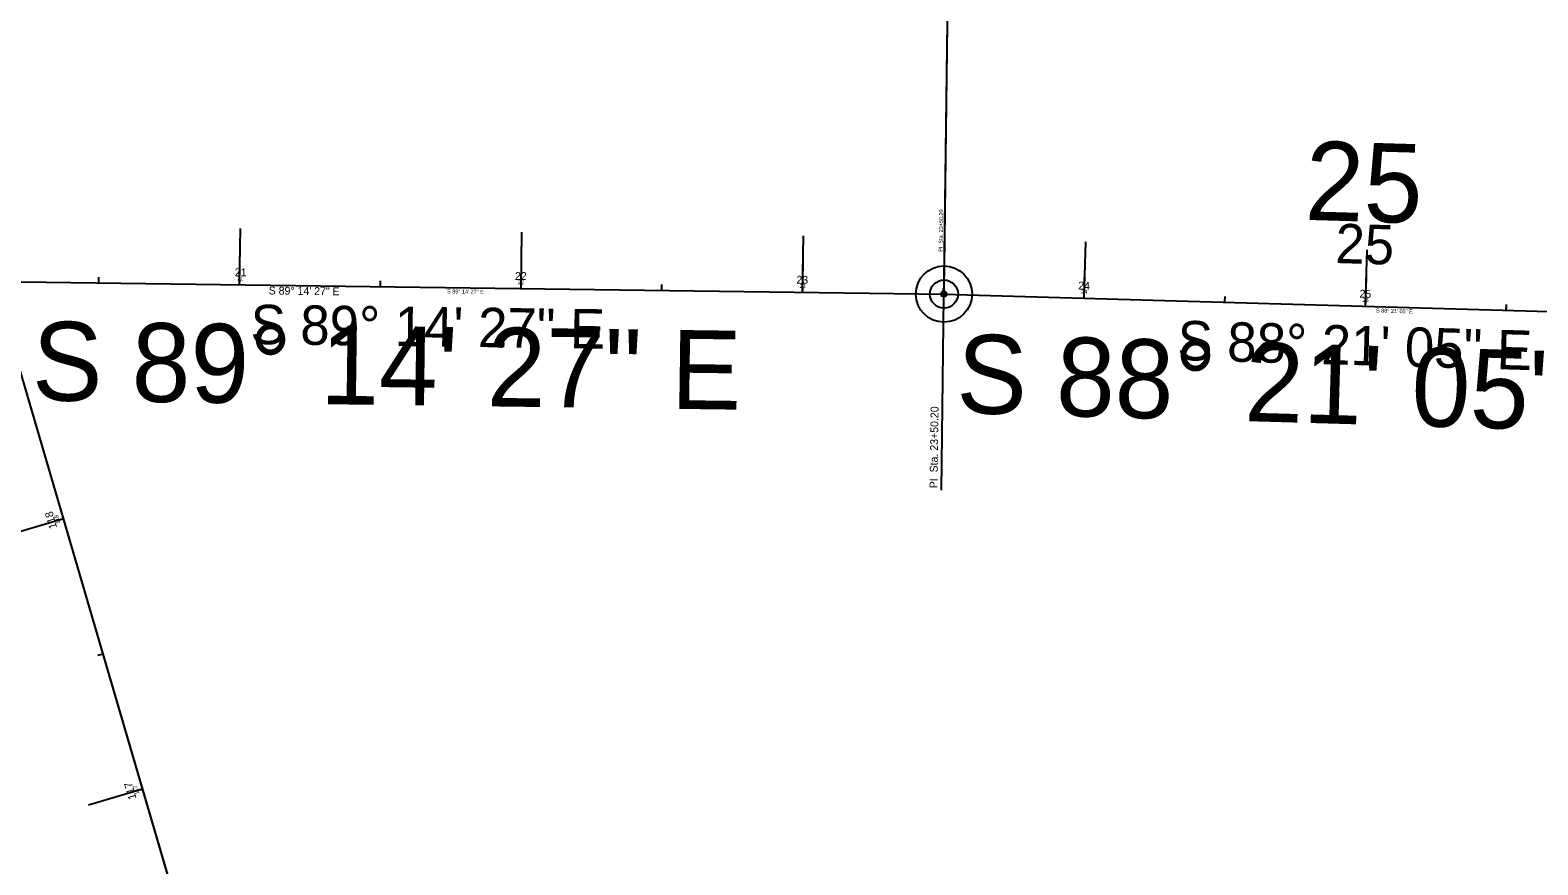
# Model space of a CAD drawing. Extents: x 1794716 to 1797874, y 325521 to 329174.
# Drawn here: x 1796283 to 1796818, y 327317 to 327614 of the extents above; entities that cross this region are included whole.
import ezdxf

# ---------------------------------------------------------------- set-up
doc = ezdxf.new("R2010")
doc.units = 0
for name, color, linetype in [('GE_P_CL_10', 7, 'Continuous'), ('GE_P_CL_100', 7, 'Continuous'), ('GE_P_CL_20', 7, 'Continuous'), ('GE_P_CL_200', 7, 'Continuous'), ('GE_P_CL_25', 7, 'Continuous'), ('GE_X_CL_30', 7, 'Continuous'), ('RW_X_CL_20', 7, 'Continuous')]:
    doc.layers.add(name, color=color, linetype=linetype)

msp = doc.modelspace()

# ---------------------------------------------------------------- linework, layer by layer
at = {"layer": 'GE_P_CL_10'}
for p, q in [((1796607.38, 327520.54), (1796607.83, 327554.83)), ((1796800.73, 325712.87), (1796269.93, 327524.51)), ((1796269.93, 327524.51), (1796607.37, 327520.04)), ((1796307.2, 327524.02), (1796307.21, 327525.02)), ((1796357.19, 327523.35), (1796357.2, 327524.35)), ((1796407.19, 327522.69), (1796407.2, 327523.69)), ((1796457.18, 327522.03), (1796457.2, 327523.03)), ((1796507.18, 327521.37), (1796507.19, 327522.37)), ((1796557.17, 327520.7), (1796557.19, 327521.7)), ((1796607.17, 327520.04), (1796607.18, 327521.04)), ((1796607.37, 327520.04), (1796930, 327510.75)), ((1796657.15, 327518.61), (1796657.18, 327519.61)), ((1796707.13, 327517.17), (1796707.16, 327518.17)), ((1796757.11, 327515.73), (1796757.14, 327516.73)), ((1796807.09, 327514.29), (1796807.12, 327515.29)), ((1796294.62, 327440.25), (1796293.66, 327439.97)), ((1796308.67, 327392.27), (1796307.72, 327391.99)), ((1796322.73, 327344.29), (1796321.77, 327344.01))]:
    msp.add_line(p, q, dxfattribs=at)
msp.add_circle((1796607.37, 327520.04), 0.5, dxfattribs=at)
at = {"layer": 'GE_P_CL_100'}
for p, q in [((1796607.43, 327525.04), (1796611.32, 327817.91)), ((1796357.19, 327523.35), (1796357.32, 327533.35)), ((1796457.18, 327522.03), (1796457.31, 327532.03)), ((1796557.17, 327520.7), (1796557.31, 327530.7)), ((1796657.15, 327518.61), (1796657.44, 327528.6)), ((1796800.73, 325712.87), (1796269.93, 327524.51)), ((1796269.93, 327524.51), (1796607.37, 327520.04)), ((1796757.11, 327515.73), (1796757.39, 327525.73)), ((1796607.37, 327520.04), (1796930, 327510.75)), ((1796294.62, 327440.25), (1796285.02, 327437.44)), ((1796322.73, 327344.29), (1796313.14, 327341.47))]:
    msp.add_line(p, q, dxfattribs=at)
msp.add_circle((1796607.37, 327520.04), 5, dxfattribs=at)
at = {"layer": 'GE_P_CL_20'}
for p, q in [((1796800.73, 325712.87), (1796269.93, 327524.51)), ((1796269.93, 327524.51), (1796607.37, 327520.04)), ((1796307.2, 327524.02), (1796307.22, 327526.02)), ((1796357.19, 327523.35), (1796357.22, 327525.35)), ((1796407.19, 327522.69), (1796407.21, 327524.69)), ((1796457.18, 327522.03), (1796457.21, 327524.03)), ((1796507.18, 327521.37), (1796507.2, 327523.37)), ((1796557.17, 327520.7), (1796557.2, 327522.7)), ((1796607.17, 327520.04), (1796607.2, 327522.04)), ((1796607.37, 327520.04), (1796930, 327510.75)), ((1796657.15, 327518.61), (1796657.21, 327520.61)), ((1796707.13, 327517.17), (1796707.19, 327519.17)), ((1796757.11, 327515.73), (1796757.16, 327517.73)), ((1796807.09, 327514.29), (1796807.14, 327516.29)), ((1796294.62, 327440.25), (1796292.7, 327439.69)), ((1796308.67, 327392.27), (1796306.76, 327391.71)), ((1796322.73, 327344.29), (1796320.81, 327343.72))]:
    msp.add_line(p, q, dxfattribs=at)
at = {"layer": 'GE_P_CL_200'}
for p, q in [((1796607.5, 327530.04), (1796615.26, 328115.78)), ((1796357.19, 327523.35), (1796357.46, 327543.35)), ((1796457.18, 327522.03), (1796457.45, 327542.03)), ((1796557.17, 327520.7), (1796557.44, 327540.7)), ((1796657.15, 327518.61), (1796657.72, 327538.6)), ((1796757.11, 327515.73), (1796757.68, 327535.72)), ((1796800.73, 325712.87), (1796269.93, 327524.51)), ((1796269.93, 327524.51), (1796607.37, 327520.04)), ((1796607.37, 327520.04), (1796930, 327510.75)), ((1796294.62, 327440.25), (1796275.42, 327434.63)), ((1796322.73, 327344.29), (1796303.54, 327338.66))]:
    msp.add_line(p, q, dxfattribs=at)
msp.add_circle((1796607.37, 327520.04), 10, dxfattribs=at)
at = {"layer": 'GE_P_CL_25'}
msp.add_line((1796606.45, 327450.47), (1796607.36, 327519.04), dxfattribs=at)
msp.add_circle((1796607.37, 327520.04), 1, dxfattribs=at)
at = {"layer": 'GE_X_CL_30'}
for p, q in [((1796269.93, 327524.51), (1796607.37, 327520.04)), ((1796607.37, 327520.04), (1796930, 327510.75))]:
    msp.add_line(p, q, dxfattribs=at)
at = {"layer": 'RW_X_CL_20'}
msp.add_lwpolyline([(1796800.73, 325712.87), (1796269.93, 327524.51)], dxfattribs=at)

# ---------------------------------------------------------------- texts
at = {"layer": 'GE_P_CL_10'}
for s, rotation, p in [('PI  Sta. 23+50.20', 89.2409, (1796606.87, 327535.05)), ('21', 359.2409, (1796356.32, 327524.87)), ('22', 359.2409, (1796456.08, 327523.54)), ('23', 359.2409, (1796556.06, 327522.22)), ('S 89%%d 14\' 27" E', 359.2409, (1796430.88, 327520.28)), ('24', 358.3515, (1796656.08, 327520.14)), ('25', 358.3515, (1796756.02, 327517.26)), ('S 88%%d 21\' 05" E', 358.3515, (1796760.83, 327513.52)), ('118', 106.3303, (1796293.51, 327438.71)), ('117', 106.3303, (1796321.64, 327342.69))]:
    msp.add_text(s, height=1.4, rotation=rotation, dxfattribs=at).set_placement(p)
at = {"layer": 'GE_P_CL_100'}
for s, rotation, p in [('25', 358.3515, (1796746.25, 327531.05)), ('S 89%%d 14\' 27" E', 359.2409, (1796361, 327502.3)), ('S 88%%d 21\' 05" E', 358.3515, (1796690.13, 327496.65))]:
    msp.add_text(s, height=14, rotation=rotation, dxfattribs=at).set_placement(p)
at = {"layer": 'GE_P_CL_20'}
for s, rotation, p in [('21', 359.2409, (1796355.46, 327526.38)), ('22', 359.2409, (1796454.98, 327525.06)), ('23', 359.2409, (1796554.94, 327523.73)), ('24', 358.3515, (1796655.01, 327521.67)), ('S 89%%d 14\' 27" E', 359.2409, (1796367.5, 327519.9)), ('25', 358.3515, (1796754.93, 327518.79)), ('118', 106.3303, (1796292.39, 327437.17)), ('117', 106.3303, (1796320.55, 327341.09))]:
    msp.add_text(s, height=2.8, rotation=rotation, dxfattribs=at).set_placement(p)
at = {"layer": 'GE_P_CL_200'}
for s, rotation, p in [('25', 358.3515, (1796735.38, 327546.37)), ('S 89%%d 14\' 27" E', 359.2409, (1796283.36, 327482.33)), ('S 88%%d 21\' 05" E', 358.3515, (1796611.58, 327477.9))]:
    msp.add_text(s, height=28, rotation=rotation, dxfattribs=at).set_placement(p)
at = {"layer": 'GE_P_CL_25'}
msp.add_text('PI  Sta. 23+50.20', height=2.8, rotation=89.2409, dxfattribs=at).set_placement((1796605.06, 327451.11))

doc.saveas('drawing.dxf')
